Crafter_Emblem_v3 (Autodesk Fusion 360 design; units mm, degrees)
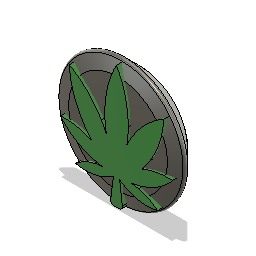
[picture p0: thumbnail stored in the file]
named bodies: "Background_2", "Batman", "Hen", "Background", "Cheese_part1", "Cheese_part2", "Cannabis"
